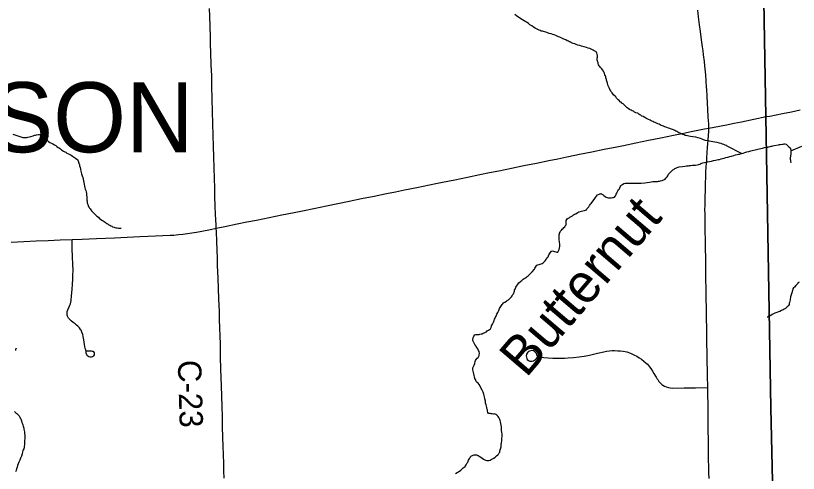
# Model space of a CAD drawing. Extents: x 103424 to 286016, y 38711 to 110967.
# Drawn here: x 139139 to 149253, y 78949 to 84863 of the extents above; entities that cross this region are included whole.
import ezdxf

# ---------------------------------------------------------------- set-up
doc = ezdxf.new("R2010")
doc.units = 0
for name, color, linetype in [('GM_X_Corporation', 7, 'Continuous'), ('GM_X_County_Road', 7, 'Continuous'), ('GM_X_County_Road_Text', 7, 'Continuous'), ('GM_X_Minor_River', 7, 'Continuous'), ('GM_X_Minor_River_Text', 7, 'Continuous'), ('GM_X_State_Route', 7, 'Continuous'), ('GM_X_Township_Road', 7, 'Continuous'), ('GM_X_Township_Text', 7, 'Continuous'), ('GM_X_US_Route', 7, 'Continuous')]:
    doc.layers.add(name, color=color, linetype=linetype)

msp = doc.modelspace()

# ---------------------------------------------------------------- linework, layer by layer
at = {"layer": 'GM_X_Corporation'}
for points in [[(151578, 71708), (149074, 71652), (149050, 72896), (149034, 73733), (149034, 73737), (149016, 74683), (148899, 79790), (148833, 83560), (148595, 97227), (148594, 97295), (158050, 97608)], [(148595, 97227), (148833, 83560), (148899, 79790), (149016, 74683), (149034, 73737), (149034, 73733), (149050, 72896), (149074, 71652), (148227, 71628), (148226, 71628), (142009, 71451), (141995, 71451), (137954, 71291)]]:
    msp.add_lwpolyline(points, dxfattribs=at)
at = {"layer": 'GM_X_County_Road'}
for points in [[(141731, 82115), (141728, 82158), (141723, 82294), (141719, 82407), (141715, 82521), (141712, 82639), (141708, 82757), (141704, 82896), (141700, 83036), (141697, 83176), (141693, 83316), (141689, 83470), (141684, 83624), (141680, 83788), (141676, 83952), (141672, 84088), (141667, 84224), (141662, 84389), (141658, 84490), (141655, 84591), (141652, 84723), (141648, 84855), (141645, 84957)], [(141834, 78887), (141831, 78982), (141829, 79077), (141825, 79190), (141822, 79302), (141818, 79407), (141813, 79559), (141810, 79685), (141807, 79811), (141803, 79945), (141798, 80079), (141795, 80186), (141792, 80293), (141788, 80456), (141785, 80618), (141781, 80724), (141778, 80830), (141775, 80935), (141772, 81040), (141765, 81205), (141760, 81337), (141755, 81469), (141749, 81634), (141746, 81733), (141742, 81832), (141738, 81951), (141733, 82071), (141731, 82115)]]:
    msp.add_lwpolyline(points, dxfattribs=at)
at = {"layer": 'GM_X_Minor_River'}
for points in [[(146766, 84059), (146764, 84071), (146760, 84087), (146753, 84099), (146747, 84117), (146745, 84127), (146738, 84137), (146734, 84147), (146724, 84163), (146712, 84177), (146697, 84193), (146687, 84205), (146679, 84215), (146670, 84229), (146668, 84243), (146666, 84253), (146662, 84265), (146659, 84275), (146655, 84289), (146655, 84313), (146658, 84325), (146658, 84337), (146656, 84352), (146654, 84362), (146649, 84378), (146645, 84390), (146635, 84398), (146617, 84409), (146604, 84415), (146592, 84423), (146578, 84429), (146560, 84437), (146539, 84444), (146515, 84452), (146487, 84460), (146452, 84467), (146428, 84475), (146405, 84482), (146383, 84490), (146363, 84498), (146342, 84504), (146324, 84511), (146310, 84519), (146296, 84525), (146283, 84531), (146267, 84537), (146249, 84548), (146224, 84558), (146206, 84568), (146188, 84575), (146172, 84583), (146153, 84591), (146137, 84599), (146119, 84607), (146100, 84614), (146080, 84620), (146058, 84628), (146033, 84633), (146005, 84643), (145946, 84660), (145930, 84664), (145916, 84670), (145904, 84675), (145889, 84683), (145871, 84691), (145853, 84703), (145832, 84715), (145810, 84732), (145783, 84746), (145765, 84760), (145748, 84772), (145730, 84783), (145710, 84795), (145689, 84807), (145669, 84821), (145648, 84834), (145628, 84846), (145610, 84860), (145589, 84876)], [(148521, 83080), (148332, 83178), (148323, 83184), (148309, 83189), (148291, 83197), (148275, 83203), (148256, 83211), (148234, 83216), (148204, 83224), (148175, 83227), (148147, 83231), (148125, 83237), (148102, 83240), (148078, 83246), (148052, 83251), (148029, 83259), (148009, 83267), (147987, 83275), (147960, 83282), (147930, 83292), (147890, 83297), (147861, 83301), (147837, 83304), (147821, 83308), (147805, 83312), (147790, 83315), (147778, 83321), (147762, 83329), (147744, 83335), (147725, 83343), (147709, 83350), (147695, 83358), (147683, 83364), (147670, 83372), (147658, 83380), (147648, 83384), (147638, 83387), (147603, 83399), (147591, 83405), (147575, 83411), (147552, 83418), (147528, 83426), (147510, 83434), (147496, 83439), (147481, 83445), (147467, 83453), (147453, 83459), (147439, 83465), (147422, 83472), (147404, 83480), (147388, 83486), (147371, 83494), (147351, 83505), (147337, 83513), (147319, 83521), (147300, 83529), (147284, 83539), (147268, 83548), (147249, 83558), (147233, 83566), (147217, 83576), (147204, 83582), (147192, 83590), (147178, 83601), (147154, 83609), (147137, 83617), (147123, 83627), (147107, 83634), (147092, 83640), (147082, 83646), (147072, 83652), (147056, 83664), (147043, 83672), (147033, 83682), (147015, 83697), (147002, 83711), (146988, 83723), (146974, 83733), (146963, 83743), (146953, 83751), (146937, 83767), (146927, 83777), (146914, 83789), (146902, 83798), (146894, 83812), (146865, 83840), (146855, 83852), (146846, 83864), (146840, 83874), (146830, 83890), (146819, 83908), (146813, 83920), (146803, 83938), (146796, 83956), (146792, 83974), (146788, 83990), (146783, 84004), (146779, 84016), (146775, 84028), (146773, 84039), (146766, 84059)], [(139101, 83333), (139217, 83293), (139233, 83289), (139245, 83287), (139268, 83287), (139282, 83290), (139298, 83294), (139318, 83298), (139336, 83301), (139364, 83311), (139376, 83314), (139386, 83318), (139396, 83320), (139410, 83324), (139428, 83327), (139442, 83329), (139485, 83308), (139495, 83300), (139506, 83290), (139520, 83278), (139532, 83264), (139547, 83252), (139563, 83238), (139581, 83224), (139602, 83213), (139620, 83205), (139641, 83193), (139657, 83183), (139673, 83172), (139690, 83160), (139704, 83150), (139718, 83140), (139732, 83130), (139745, 83122), (139759, 83112), (139773, 83105), (139788, 83097), (139802, 83087), (139822, 83077), (139839, 83067), (139857, 83058), (139873, 83048), (139887, 83038), (139898, 83032), (139914, 83020), (139930, 83010), (139939, 82999), (139947, 82985), (139949, 82974), (139953, 82962), (139958, 82950), (139962, 82938), (139966, 82922), (139971, 82902), (139975, 82880), (139982, 82852), (139990, 82818), (139999, 82794), (140005, 82771), (140010, 82749), (140016, 82727), (140021, 82707), (140034, 82639), (140038, 82621), (140045, 82602), (140049, 82586), (140053, 82564), (140056, 82544), (140058, 82522), (140059, 82500), (140059, 82479), (140061, 82465), (140061, 82455), (140064, 82445), (140066, 82433), (140070, 82423), (140074, 82413), (140078, 82401), (140089, 82385), (140095, 82375), (140101, 82365), (140112, 82353), (140120, 82341), (140130, 82329), (140143, 82317), (140155, 82305), (140169, 82290), (140186, 82274), (140208, 82258), (140220, 82246), (140237, 82234), (140251, 82222), (140268, 82211), (140282, 82201), (140294, 82193), (140306, 82185), (140319, 82177), (140335, 82167), (140345, 82159), (140357, 82154), (140370, 82148)], [(147824, 82922), (147834, 82924), (147848, 82925), (147864, 82927), (147884, 82929), (147908, 82930), (147926, 82932), (147967, 82941), (147979, 82945), (147993, 82951), (148007, 82956), (148021, 82960), (148039, 82964), (148057, 82969), (148081, 82973), (148107, 82980), (148133, 82984), (148157, 82991), (148181, 82995), (148200, 82998), (148218, 83002), (148236, 83006), (148254, 83011), (148274, 83015), (148294, 83021), (148316, 83028), (148342, 83034), (148368, 83043), (148390, 83049), (148420, 83056), (148443, 83063), (148463, 83067), (148481, 83071), (148495, 83074), (148507, 83076), (148521, 83080), (148541, 83086), (148563, 83093), (148587, 83101), (148615, 83108), (148641, 83117), (148672, 83123), (148694, 83128), (148712, 83132), (148728, 83136), (148746, 83141), (148768, 83147), (148792, 83152), (148816, 83158), (148840, 83163), (148860, 83165), (148874, 83169), (148891, 83172), (148901, 83176), (148911, 83178), (148923, 83182), (148943, 83187), (148999, 83194), (149009, 83196), (149025, 83196), (149047, 83201), (149057, 83203), (149070, 83205), (149080, 83207), (149096, 83204), (149106, 83194), (149118, 83182), (149131, 83168), (149147, 83156), (149153, 83140), (149158, 83128), (149158, 83118), (149156, 83102), (149156, 83089), (149155, 83077), (149151, 83049), (149149, 83027), (149148, 83009), (149150, 82994), (149152, 82980), (149152, 82980), (149152, 82978), (149157, 82962)], [(149158, 83118), (149298, 83177)], [(146254, 82215), (146268, 82236), (146280, 82244), (146290, 82250), (146302, 82258), (146316, 82269), (146334, 82277), (146348, 82287), (146362, 82296), (146376, 82304), (146394, 82315), (146404, 82321), (146416, 82327), (146432, 82331), (146452, 82338), (146470, 82342), (146492, 82347), (146504, 82349), (146514, 82355), (146522, 82365), (146532, 82378), (146544, 82394), (146556, 82410), (146567, 82425), (146577, 82437), (146585, 82449), (146615, 82488), (146625, 82501), (146632, 82513), (146646, 82529), (146660, 82546), (146670, 82552), (146686, 82560), (146696, 82562), (146706, 82563), (146716, 82557), (146731, 82547), (146741, 82537), (146755, 82527), (146769, 82519), (146784, 82513), (146798, 82510), (146812, 82508), (146836, 82510), (146850, 82513), (146866, 82515), (146876, 82519), (146888, 82530), (146894, 82540), (146900, 82554), (146906, 82568), (146912, 82584), (146921, 82599), (146931, 82611), (146941, 82627), (146947, 82640), (146953, 82650), (146961, 82662), (146972, 82676), (146982, 82683), (147000, 82693), (147014, 82697), (147029, 82700), (147045, 82700), (147107, 82699), (147134, 82698), (147162, 82698), (147190, 82699), (147222, 82699), (147269, 82704), (147301, 82707), (147329, 82711), (147353, 82716), (147375, 82718), (147391, 82718), (147406, 82719), (147420, 82719), (147434, 82721), (147446, 82723), (147460, 82726), (147474, 82730), (147492, 82734), (147504, 82739), (147516, 82743), (147532, 82751), (147542, 82763), (147558, 82782), (147566, 82794), (147577, 82815), (147601, 82841), (147619, 82858), (147633, 82870), (147643, 82874), (147659, 82887), (147669, 82891), (147689, 82899), (147715, 82908), (147757, 82915), (147785, 82919), (147807, 82922), (147824, 82922)], [(140370, 82148), (140380, 82142), (140390, 82136), (140410, 82128), (140422, 82124), (140437, 82123), (140451, 82119), (140467, 82117), (140477, 82117), (140499, 82118), (140499, 82118), (140501, 82118)], [(145309, 80895), (145317, 80911), (145323, 80924), (145329, 80940), (145337, 80954), (145342, 80966), (145348, 80981), (145356, 81005), (145370, 81027), (145381, 81054), (145393, 81078), (145424, 81129), (145434, 81140), (145444, 81150), (145460, 81160), (145482, 81175), (145492, 81181), (145508, 81192), (145522, 81204), (145538, 81220), (145546, 81231), (145555, 81243), (145565, 81259), (145573, 81270), (145577, 81280), (145581, 81290), (145585, 81302), (145586, 81314), (145592, 81328), (145598, 81343), (145604, 81353), (145612, 81367), (145624, 81384), (145631, 81398), (145643, 81412), (145657, 81425), (145667, 81433), (145681, 81441), (145699, 81456), (145711, 81466), (145727, 81474), (145741, 81485), (145751, 81493), (145763, 81501), (145779, 81518), (145788, 81528), (145802, 81538), (145814, 81551), (145844, 81585), (145850, 81602), (145856, 81614), (145865, 81628), (145875, 81637), (145887, 81643), (145903, 81649), (145917, 81653), (145931, 81658), (145941, 81662), (145955, 81670), (145965, 81677), (145981, 81693), (145993, 81711), (145997, 81722), (146007, 81734), (146021, 81746), (146026, 81760), (146030, 81771), (146036, 81785), (146046, 81799), (146062, 81818), (146078, 81822), (146090, 81818), (146104, 81814), (146118, 81811), (146133, 81807), (146147, 81807), (146154, 81825), (146162, 81842), (146168, 81864), (146172, 81878), (146173, 81890), (146173, 81900), (146166, 81943), (146164, 81961), (146162, 81987), (146161, 82011), (146163, 82030), (146165, 82042), (146168, 82054), (146176, 82066), (146182, 82080), (146192, 82093), (146202, 82105), (146214, 82113), (146224, 82124), (146236, 82136), (146241, 82146), (146251, 82162), (146251, 82183), (146251, 82197), (146254, 82215)], [(149265, 81419), (149249, 81410), (149245, 81400), (149223, 81378), (149202, 81355), (149190, 81347), (149182, 81334), (149176, 81310), (149169, 81282), (149151, 81231), (149150, 81219), (149148, 81202), (149146, 81190)], [(149146, 81190), (149142, 81174), (149141, 81158), (149137, 81146), (149133, 81131), (149127, 81119), (149121, 81107), (149109, 81099), (149099, 81093), (149087, 81080), (149071, 81070), (149058, 81061), (149035, 81051), (149013, 81042), (148995, 81034), (148977, 81028), (148961, 81021), (148951, 81017), (148931, 81009), (148915, 81000), (148899, 80990), (148881, 80982), (148869, 80975), (148855, 80965), (148851, 80965)], [(145411, 79293), (145413, 79307), (145412, 79323), (145416, 79343), (145420, 79370), (145423, 79398), (145425, 79426), (145424, 79455), (145422, 79481), (145419, 79503), (145417, 79525), (145416, 79550), (145412, 79572), (145410, 79592), (145405, 79614), (145399, 79632), (145392, 79652), (145382, 79670), (145374, 79684), (145357, 79700), (145343, 79710), (145329, 79716), (145314, 79715), (145296, 79719), (145284, 79719), (145272, 79721), (145260, 79722), (145250, 79722), (145241, 79736), (145237, 79752), (145235, 79771), (145230, 79787), (145226, 79801), (145222, 79817), (145218, 79833), (145211, 79855), (145209, 79883), (145204, 79911), (145198, 79938), (145189, 79972), (145180, 79998), (145168, 80024), (145128, 80098), (145114, 80114), (145103, 80122), (145089, 80136), (145081, 80160), (145074, 80176), (145070, 80194), (145063, 80214), (145059, 80234), (145055, 80252), (145050, 80270), (145048, 80286), (145046, 80296), (145048, 80311), (145057, 80329), (145065, 80345), (145071, 80370), (145076, 80394), (145082, 80408), (145090, 80418), (145104, 80437), (145114, 80445), (145124, 80461), (145127, 80472), (145129, 80482), (145131, 80496), (145129, 80522), (145120, 80538), (145110, 80558), (145099, 80576), (145091, 80588), (145085, 80598), (145074, 80612), (145054, 80650), (145045, 80666), (145049, 80684), (145053, 80699), (145060, 80723), (145072, 80737), (145084, 80742), (145096, 80742), (145106, 80742), (145118, 80744), (145129, 80744), (145139, 80747), (145153, 80751), (145167, 80753), (145181, 80759), (145195, 80764), (145211, 80772), (145223, 80778), (145233, 80789), (145249, 80801), (145263, 80807), (145275, 80816), (145282, 80834), (145290, 80854), (145300, 80875), (145309, 80895)], [(139145, 80566), (139145, 80562), (139139, 80554), (139135, 80538)], [(139125, 79748), (139142, 79732), (139154, 79722), (139164, 79714), (139176, 79700), (139183, 79690), (139191, 79676), (139199, 79664), (139206, 79652), (139210, 79640), (139214, 79626), (139220, 79608), (139229, 79590), (139233, 79574), (139237, 79560), (139242, 79546), (139244, 79534), (139246, 79520), (139251, 79503), (139253, 79485), (139255, 79463), (139256, 79441), (139256, 79421), (139257, 79396), (139255, 79376), (139255, 79358), (139253, 79344), (139254, 79330), (139248, 79289), (139243, 79265), (139237, 79255), (139233, 79245), (139229, 79226), (139224, 79202), (139214, 79173), (139203, 79147), (139193, 79121), (139181, 79094), (139172, 79070), (139164, 79049), (139158, 79029), (139151, 79007), (139145, 78986), (139137, 78968)], [(144824, 78945), (144844, 78961), (144860, 78970), (144894, 78991), (144906, 79003), (144923, 79019), (144933, 79030), (144947, 79038), (144961, 79057), (144967, 79069), (144975, 79083), (144983, 79095), (144986, 79105), (144992, 79120), (145000, 79134), (145008, 79146), (145014, 79158), (145030, 79175), (145042, 79181), (145052, 79185), (145064, 79188), (145082, 79190), (145094, 79188), (145104, 79186), (145116, 79181), (145128, 79173), (145151, 79159), (145167, 79145), (145186, 79133), (145200, 79123), (145210, 79120), (145228, 79114), (145240, 79114), (145255, 79116), (145271, 79121), (145285, 79127), (145301, 79135), (145319, 79146), (145335, 79160), (145354, 79175), (145368, 79187), (145380, 79199), (145388, 79212), (145394, 79224), (145398, 79238), (145407, 79277), (145411, 79293)]]:
    msp.add_lwpolyline(points, dxfattribs=at)
at = {"layer": 'GM_X_State_Route'}
for points in [[(148097, 83410), (148095, 83467), (148090, 83551), (148085, 83648), (148080, 83735), (148075, 83819), (148069, 83912), (148068, 83936), (148062, 84022), (148056, 84097), (148046, 84216), (148040, 84272), (148029, 84357), (148023, 84406), (148016, 84458), (148004, 84551), (147990, 84659), (147978, 84746), (147965, 84849), (147954, 84933)], [(148064, 82896), (148064, 82907), (148068, 82955), (148070, 82989), (148072, 83027), (148077, 83095), (148081, 83163), (148084, 83202), (148088, 83260), (148091, 83313), (148095, 83372), (148097, 83410)], [(148099, 78883), (148098, 78956), (148096, 79039), (148094, 79122), (148093, 79235), (148092, 79320), (148092, 79402), (148090, 79484), (148088, 79573), (148087, 79681), (148086, 79748), (148086, 79870), (148085, 79934), (148084, 80012), (148083, 80057), (148082, 80106), (148081, 80164), (148080, 80212), (148079, 80289), (148077, 80380), (148076, 80458), (148075, 80527), (148073, 80610), (148072, 80682), (148071, 80767), (148069, 80850), (148068, 80922), (148067, 81001), (148066, 81066), (148065, 81119), (148064, 81172), (148063, 81235), (148062, 81298), (148062, 81357), (148060, 81435), (148060, 81495), (148058, 81567), (148057, 81663), (148056, 81761), (148055, 81825), (148054, 81897), (148052, 81977), (148051, 82065), (148050, 82131), (148049, 82222), (148048, 82303), (148047, 82358), (148048, 82409), (148050, 82519), (148052, 82608), (148054, 82701), (148057, 82773), (148060, 82853), (148064, 82896)]]:
    msp.add_lwpolyline(points, dxfattribs=at)
at = {"layer": 'GM_X_Township_Road'}
for points in [[(140045, 80531), (140048, 80504), (140050, 80495), (140053, 80488), (140060, 80478), (140073, 80466), (140085, 80459), (140101, 80456), (140119, 80455), (140131, 80458), (140141, 80463), (140148, 80467), (140157, 80481), (140160, 80492), (140158, 80507), (140149, 80519), (140141, 80523), (140133, 80525), (140117, 80527), (140092, 80527), (140063, 80528), (140058, 80529), (140052, 80532), (140047, 80537), (140044, 80543), (140037, 80563), (140030, 80612), (140021, 80672), (140012, 80715), (140005, 80745), (139995, 80771), (139984, 80798), (139976, 80809), (139962, 80829), (139943, 80849), (139926, 80865), (139908, 80879), (139883, 80900), (139858, 80919), (139846, 80929), (139835, 80939), (139822, 80953), (139816, 80964), (139810, 80979), (139806, 80993), (139803, 81010), (139803, 81025), (139806, 81042), (139813, 81062), (139832, 81102), (139840, 81122), (139846, 81141), (139851, 81161), (139856, 81184), (139861, 81241), (139868, 81326), (139874, 81392), (139878, 81456), (139880, 81513), (139881, 81566), (139878, 81655), (139875, 81743), (139871, 81857), (139868, 81971)], [(145889, 80452), (145874, 80482), (145868, 80496), (145861, 80508), (145852, 80516), (145844, 80523), (145831, 80530), (145811, 80535), (145780, 80528), (145768, 80522), (145757, 80514), (145747, 80501), (145739, 80487), (145737, 80467), (145739, 80450), (145745, 80432), (145751, 80419), (145765, 80407), (145783, 80400), (145800, 80397), (145815, 80398), (145830, 80401), (145846, 80412), (145857, 80421), (145870, 80434), (145878, 80444), (145898, 80451), (145924, 80449), (145965, 80445), (146019, 80443), (146079, 80439), (146139, 80436), (146231, 80437), (146278, 80440), (146350, 80444), (146423, 80453), (146484, 80464), (146554, 80477), (146659, 80501), (146738, 80519), (146774, 80527), (146812, 80532), (146846, 80535), (146878, 80535), (146920, 80534), (146952, 80532), (146991, 80528), (147038, 80517), (147084, 80501), (147129, 80482), (147167, 80462), (147198, 80443), (147227, 80424), (147258, 80400), (147289, 80374), (147303, 80359), (147318, 80342), (147332, 80325), (147348, 80302), (147369, 80270), (147387, 80240), (147408, 80204), (147417, 80191), (147426, 80176), (147436, 80161), (147451, 80135), (147469, 80117), (147489, 80097), (147504, 80088), (147522, 80077), (147547, 80068), (147575, 80059), (147597, 80054), (147629, 80051), (147776, 80053), (147924, 80054), (148083, 80057)]]:
    msp.add_lwpolyline(points, dxfattribs=at)
at = {"layer": 'GM_X_US_Route'}
for points in [[(148097, 83410), (148165, 83423), (148327, 83454), (148423, 83473), (148519, 83492), (148679, 83525), (148838, 83558)], [(148097, 83410), (148165, 83423), (148327, 83454), (148423, 83473), (148519, 83492), (148679, 83525), (148838, 83558)], [(148838, 83558), (148886, 83566), (149047, 83599), (149163, 83622), (149278, 83645)], [(148838, 83558), (148886, 83566), (149047, 83599), (149163, 83622), (149278, 83645)], [(146283, 83042), (146424, 83071), (146585, 83104), (146746, 83136), (146906, 83169), (146992, 83187), (147154, 83220), (147316, 83253), (147477, 83286), (147639, 83319), (147753, 83342), (147867, 83365), (147954, 83382), (148041, 83399), (148097, 83410)], [(146283, 83042), (146424, 83071), (146585, 83104), (146746, 83136), (146906, 83169), (146992, 83187), (147154, 83220), (147316, 83253), (147477, 83286), (147639, 83319), (147753, 83342), (147867, 83365), (147954, 83382), (148041, 83399), (148097, 83410)], [(139081, 81937), (139246, 81945), (139403, 81952), (139559, 81959), (139713, 81965), (139868, 81971), (140000, 81976), (140091, 81980), (140182, 81984), (140299, 81989), (140415, 81994), (140580, 82001), (140745, 82008), (140846, 82013), (140947, 82017), (141042, 82021), (141137, 82025), (141184, 82028), (141242, 82033), (141301, 82040), (141360, 82047), (141417, 82056), (141477, 82066), (141544, 82079), (141657, 82101), (141731, 82115), (141840, 82138), (142002, 82171), (142128, 82197), (142253, 82222), (142415, 82255), (142577, 82288), (142739, 82321), (142867, 82347), (142994, 82373), (143156, 82405), (143302, 82435), (143448, 82465), (143610, 82498), (143771, 82531), (143933, 82564), (144048, 82587), (144164, 82611), (144325, 82644), (144487, 82676), (144570, 82693), (144653, 82710), (144815, 82743), (144977, 82776), (145139, 82809), (145261, 82834), (145384, 82859), (145545, 82892), (145707, 82925), (145869, 82958), (146031, 82991), (146146, 83014), (146262, 83038), (146283, 83042)], [(139081, 81937), (139246, 81945), (139403, 81952), (139559, 81959), (139713, 81965), (139868, 81971), (140000, 81976), (140091, 81980), (140182, 81984), (140299, 81989), (140415, 81994), (140580, 82001), (140745, 82008), (140846, 82013), (140947, 82017), (141042, 82021), (141137, 82025), (141184, 82028), (141242, 82033), (141301, 82040), (141360, 82047), (141417, 82056), (141477, 82066), (141544, 82079), (141657, 82101), (141731, 82115), (141840, 82138), (142002, 82171), (142128, 82197), (142253, 82222), (142415, 82255), (142577, 82288), (142739, 82321), (142867, 82347), (142994, 82373), (143156, 82405), (143302, 82435), (143448, 82465), (143610, 82498), (143771, 82531), (143933, 82564), (144048, 82587), (144164, 82611), (144325, 82644), (144487, 82676), (144570, 82693), (144653, 82710), (144815, 82743), (144977, 82776), (145139, 82809), (145261, 82834), (145384, 82859), (145545, 82892), (145707, 82925), (145869, 82958), (146031, 82991), (146146, 83014), (146262, 83038), (146283, 83042)]]:
    msp.add_lwpolyline(points, dxfattribs=at)

# ---------------------------------------------------------------- texts
at = {"layer": 'GM_X_County_Road_Text'}
msp.add_text('C-23', height=301.9, rotation=271.7153, dxfattribs=at).set_placement((141234, 80410))
at = {"layer": 'GM_X_Minor_River_Text'}
msp.add_text('Butternut', height=503.5, rotation=49.4982, dxfattribs=at).set_placement((145735, 80172))
at = {"layer": 'GM_X_Township_Text'}
msp.add_text('MUNSON', height=905.6, rotation=0, dxfattribs=at).set_placement((136058, 83097))

doc.saveas('drawing.dxf')
